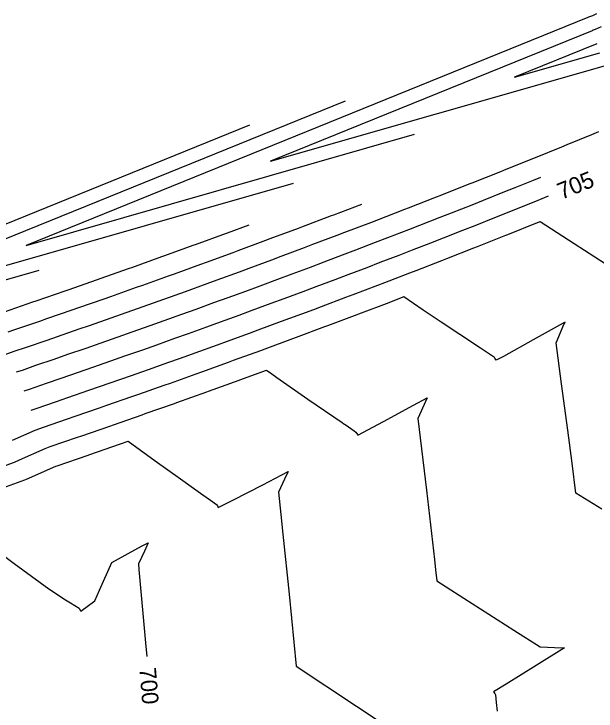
# Model space of a CAD drawing. Extents: x 1487507 to 1489130, y 497211 to 499439.
# Drawn here: x 1488139.6 to 1488223.8, y 498566.4 to 498667.3 of the extents above; entities that cross this region are included whole.
import ezdxf

# ---------------------------------------------------------------- set-up
doc = ezdxf.new("R2010")
doc.units = 0
for name, color, linetype in [('Prop CMT Ditch DDE', 7, 'Continuous'), ('Prop Drainage Ditch Flow Line', 7, 'Continuous'), ('Prop Drainage Structure Pipe Outlet Channel Detail CELL', 7, 'Continuous')]:
    doc.layers.add(name, color=color, linetype=linetype)

msp = doc.modelspace()

# ---------------------------------------------------------------- linework, layer by layer
at = {"layer": 'Prop CMT Ditch DDE'}
for points in [[(1488223.87, 498667.33), (1488223.27, 498667.08), (1488222.99, 498666.97), (1488222.72, 498666.85), (1488222.6, 498666.8), (1488141.33, 498633.84), (1488197.55, 498649.91)], [(1488224.54, 498665.45), (1488223.65, 498665.08), (1488223.26, 498664.92), (1488223.25, 498664.91), (1488176.67, 498646.02), (1488225, 498659.83)], [(1488223.9, 498663.02), (1488212.01, 498658.2), (1488224.35, 498661.72)], [(1488187.5, 498654.72), (1488115.64, 498625.58)], [(1488224.16, 498650.27), (1488223.15, 498649.85), (1488219.58, 498648.38), (1488218.78, 498648.06), (1488214.99, 498646.52), (1488214.38, 498646.27), (1488210.4, 498644.67), (1488209.98, 498644.5), (1488205.81, 498642.84), (1488205.41, 498642.68), (1488201.21, 498641.02), (1488200.67, 498640.81), (1488196.61, 498639.22), (1488196.08, 498639.02), (1488192.01, 498637.45), (1488191.14, 498637.11), (1488187.4, 498635.68), (1488186.28, 498635.25), (1488182.79, 498633.94), (1488181.56, 498633.47), (1488178.18, 498632.21), (1488176.84, 498631.71), (1488173.57, 498630.5), (1488172.14, 498629.98), (1488168.95, 498628.81), (1488167.5, 498628.28), (1488164.33, 498627.13), (1488162.86, 498626.6), (1488159.7, 498625.47), (1488158.22, 498624.95), (1488155.08, 498623.83), (1488153.58, 498623.31), (1488150.45, 498622.21), (1488148.95, 498621.69), (1488145.81, 498620.6), (1488144.31, 498620.08), (1488141.18, 498619.02), (1488139.72, 498618.51), (1488136.55, 498617.43)], [(1488215.78, 498643.66), (1488214.71, 498643.23), (1488212.05, 498642.16), (1488210.33, 498641.47), (1488207.45, 498640.32), (1488205.83, 498639.68), (1488202.84, 498638.5), (1488201.18, 498637.85), (1488198.23, 498636.7), (1488196.65, 498636.08), (1488193.62, 498634.92), (1488191.83, 498634.23), (1488189.01, 498633.15), (1488187.07, 498632.41), (1488184.39, 498631.4), (1488182.41, 498630.65), (1488179.77, 498629.66), (1488177.73, 498628.91), (1488175.14, 498627.95), (1488173.07, 498627.18), (1488170.52, 498626.25), (1488168.45, 498625.5), (1488165.89, 498624.57), (1488163.83, 498623.83), (1488161.25, 498622.91), (1488159.21, 498622.18), (1488156.62, 498621.26), (1488154.58, 498620.54), (1488151.98, 498619.63), (1488149.96, 498618.92), (1488147.34, 498618.02), (1488145.33, 498617.33), (1488142.7, 498616.43), (1488140.74, 498615.75), (1488139.91, 498615.47)], [(1488179.98, 498642.81), (1488116, 498624.52)], [(1488189.85, 498639.77), (1488185.8, 498638.22), (1488185.49, 498638.1), (1488181.2, 498636.48), (1488180.72, 498636.3), (1488176.59, 498634.76), (1488175.95, 498634.52), (1488171.99, 498633.05), (1488171.22, 498632.77), (1488167.38, 498631.36), (1488166.56, 498631.06), (1488162.76, 498629.69), (1488161.9, 498629.38), (1488158.15, 498628.04), (1488157.24, 498627.72), (1488153.53, 498626.41), (1488152.59, 498626.07), (1488148.91, 498624.79), (1488147.94, 498624.45), (1488144.29, 498623.19), (1488143.29, 498622.84), (1488139.66, 498621.6), (1488138.7, 498621.27)], [(1488142.04, 498609.97), (1488142.78, 498610.23), (1488145.73, 498611.25), (1488147.36, 498611.81), (1488150.39, 498612.86), (1488151.97, 498613.4), (1488155.05, 498614.48), (1488156.58, 498615.01), (1488159.71, 498616.12), (1488161.17, 498616.63), (1488164.36, 498617.77), (1488165.77, 498618.28), (1488169.01, 498619.45), (1488170.35, 498619.93), (1488173.66, 498621.14), (1488174.92, 498621.6), (1488178.3, 498622.85), (1488179.51, 498623.29), (1488182.94, 498624.57), (1488184.09, 498625), (1488187.58, 498626.32), (1488188.65, 498626.72), (1488192.22, 498628.08), (1488193.22, 498628.46), (1488196.85, 498629.86), (1488197.78, 498630.22), (1488201.48, 498631.65), (1488202.22, 498631.94), (1488206.1, 498633.47), (1488206.65, 498633.68), (1488210.73, 498635.3), (1488211.03, 498635.42), (1488215.34, 498637.15), (1488215.37, 498637.16), (1488215.72, 498637.3), (1488220.62, 498634.11), (1488225.13, 498631.21)], [(1488173.57, 498636.77), (1488170.41, 498635.6), (1488170.29, 498635.56), (1488165.81, 498633.92), (1488165.61, 498633.85), (1488161.2, 498632.26), (1488160.93, 498632.16), (1488156.6, 498630.61), (1488156.25, 498630.49), (1488151.99, 498628.98), (1488151.59, 498628.84), (1488147.37, 498627.37), (1488146.93, 498627.21), (1488142.76, 498625.77), (1488142.27, 498625.6), (1488138.14, 498624.19)], [(1488224.62, 498595.65), (1488220.89, 498597.97), (1488220.34, 498602.31), (1488219.7, 498607.1), (1488218.82, 498613.82), (1488218.02, 498619.71), (1488219.16, 498622.36), (1488219.32, 498622.72), (1488219.03, 498622.56), (1488214.72, 498620.16), (1488210.4, 498617.77), (1488209.36, 498617.2), (1488209.15, 498617.51), (1488209.09, 498617.62), (1488207.8, 498618.47), (1488207.06, 498618.96), (1488204.09, 498620.93), (1488201.39, 498622.74), (1488198.8, 498624.47), (1488195.98, 498626.37), (1488193.91, 498625.58), (1488193.82, 498625.54), (1488189.44, 498623.87), (1488189.18, 498623.78), (1488184.93, 498622.18), (1488184.53, 498622.03), (1488180.4, 498620.49), (1488179.88, 498620.3), (1488175.85, 498618.81), (1488175.23, 498618.58), (1488171.3, 498617.15), (1488170.57, 498616.89), (1488166.73, 498615.5), (1488165.91, 498615.21), (1488162.16, 498613.86), (1488161.25, 498613.54), (1488157.58, 498612.25), (1488156.59, 498611.9), (1488152.98, 498610.64), (1488151.92, 498610.27), (1488148.38, 498609.05), (1488147.25, 498608.67), (1488143.8, 498607.47), (1488142.59, 498607.05), (1488139.32, 498605.59)], [(1488135.84, 498601.11), (1488139.65, 498602.47), (1488140.36, 498602.79), (1488144.1, 498604.46), (1488144.82, 498604.71), (1488148.77, 498606.08), (1488149.4, 498606.29), (1488153.45, 498607.69), (1488153.99, 498607.88), (1488158.12, 498609.32), (1488158.57, 498609.48), (1488162.8, 498610.97), (1488163.14, 498611.09), (1488167.47, 498612.64), (1488167.7, 498612.72), (1488172.14, 498614.32), (1488172.25, 498614.36), (1488176.1, 498615.77), (1488176.88, 498615.22), (1488177.6, 498614.73), (1488182.1, 498611.59), (1488187.05, 498608.18), (1488187.15, 498608.12), (1488187.62, 498607.79), (1488188.82, 498606.97), (1488189.06, 498606.81), (1488189.29, 498606.44), (1488189.32, 498606.38), (1488193.06, 498608.36), (1488197.4, 498610.69), (1488199.36, 498611.75), (1488198.27, 498609.31), (1488198.02, 498608.76), (1488199.26, 498598.42), (1488200.4, 498588.38), (1488200.57, 498586.88), (1488200.75, 498585.28), (1488202.1, 498584.41), (1488204.69, 498582.75), (1488211.91, 498578.14), (1488215.7, 498575.74), (1488218.86, 498575.59), (1488219.21, 498575.58), (1488215.11, 498573.01), (1488210.81, 498570.34), (1488208.98, 498569.21), (1488209.13, 498568.97), (1488209.25, 498568.78), (1488209.37, 498567.65), (1488209.49, 498566.4)], [(1488136.85, 498598.34), (1488141.15, 498599.88), (1488141.4, 498599.99), (1488145.61, 498601.87), (1488145.84, 498601.95), (1488150.29, 498603.49), (1488150.42, 498603.54), (1488154.98, 498605.11), (1488155, 498605.12), (1488156.08, 498605.49), (1488160.02, 498602.65), (1488163.65, 498600.06), (1488165.2, 498598.94), (1488166.9, 498597.73), (1488168.01, 498596.94), (1488168.89, 498596.32), (1488169.01, 498596.12), (1488169.14, 498595.89), (1488171.22, 498596.95), (1488175.6, 498599.2), (1488179.25, 498601.1), (1488178.74, 498600), (1488177.87, 498598.13), (1488178.21, 498594.88), (1488178.49, 498592.06), (1488179.39, 498583.33), (1488180.4, 498572.92), (1488189.12, 498567.13), (1488195.19, 498563.14)]]:
    msp.add_lwpolyline(points, dxfattribs=at)
at = {"layer": 'Prop Drainage Ditch Flow Line'}
for points in [[(1488114.99, 498627.47), (1488173.68, 498651.27)], [(1488216.88, 498640.94), (1488215.04, 498640.19), (1488213.7, 498639.65), (1488210.68, 498638.44), (1488209.09, 498637.81), (1488206.24, 498636.68), (1488204.47, 498635.99), (1488201.7, 498634.9), (1488199.86, 498634.18), (1488197.21, 498633.15), (1488195.24, 498632.39), (1488192.53, 498631.34), (1488190.61, 498630.61), (1488187.86, 498629.56), (1488185.99, 498628.86), (1488183.25, 498627.83), (1488181.36, 498627.12), (1488178.62, 498626.1), (1488176.72, 498625.4), (1488174, 498624.39), (1488172.09, 498623.69), (1488169.4, 498622.71), (1488167.45, 498622.01), (1488164.8, 498621.05), (1488162.81, 498620.34), (1488160.19, 498619.4), (1488158.16, 498618.69), (1488155.58, 498617.78), (1488153.52, 498617.06), (1488150.96, 498616.16), (1488148.87, 498615.44), (1488146.34, 498614.57), (1488144.22, 498613.84), (1488141.76, 498612.99), (1488140.98, 498612.72)], [(1488143.17, 498630.21), (1488122.43, 498624.28), (1488122.34, 498624.26)], [(1488134.82, 498591.38), (1488139.59, 498587.8), (1488144.6, 498584.1), (1488147.05, 498582.54), (1488147.73, 498582.11), (1488148.99, 498581.31), (1488149.11, 498581.09), (1488149.24, 498580.87), (1488151.27, 498582.37), (1488151.95, 498583.92), (1488153.72, 498587.93), (1488158.03, 498590.29), (1488159, 498590.77), (1488158.44, 498589.6), (1488157.58, 498587.76), (1488157.65, 498586.93), (1488158.62, 498576.29), (1488158.78, 498574.35)]]:
    msp.add_lwpolyline(points, dxfattribs=at)

# ---------------------------------------------------------------- texts
at = {"layer": 'Prop Drainage Structure Pipe Outlet Channel Detail CELL'}
for s, rotation, p in [('705', 22.0973, (1488218.8, 498640.43)), ('700', 274.6604, (1488157.71, 498572.65))]:
    msp.add_text(s, height=2.4, rotation=rotation, dxfattribs=at).set_placement(p)

doc.saveas('drawing.dxf')
